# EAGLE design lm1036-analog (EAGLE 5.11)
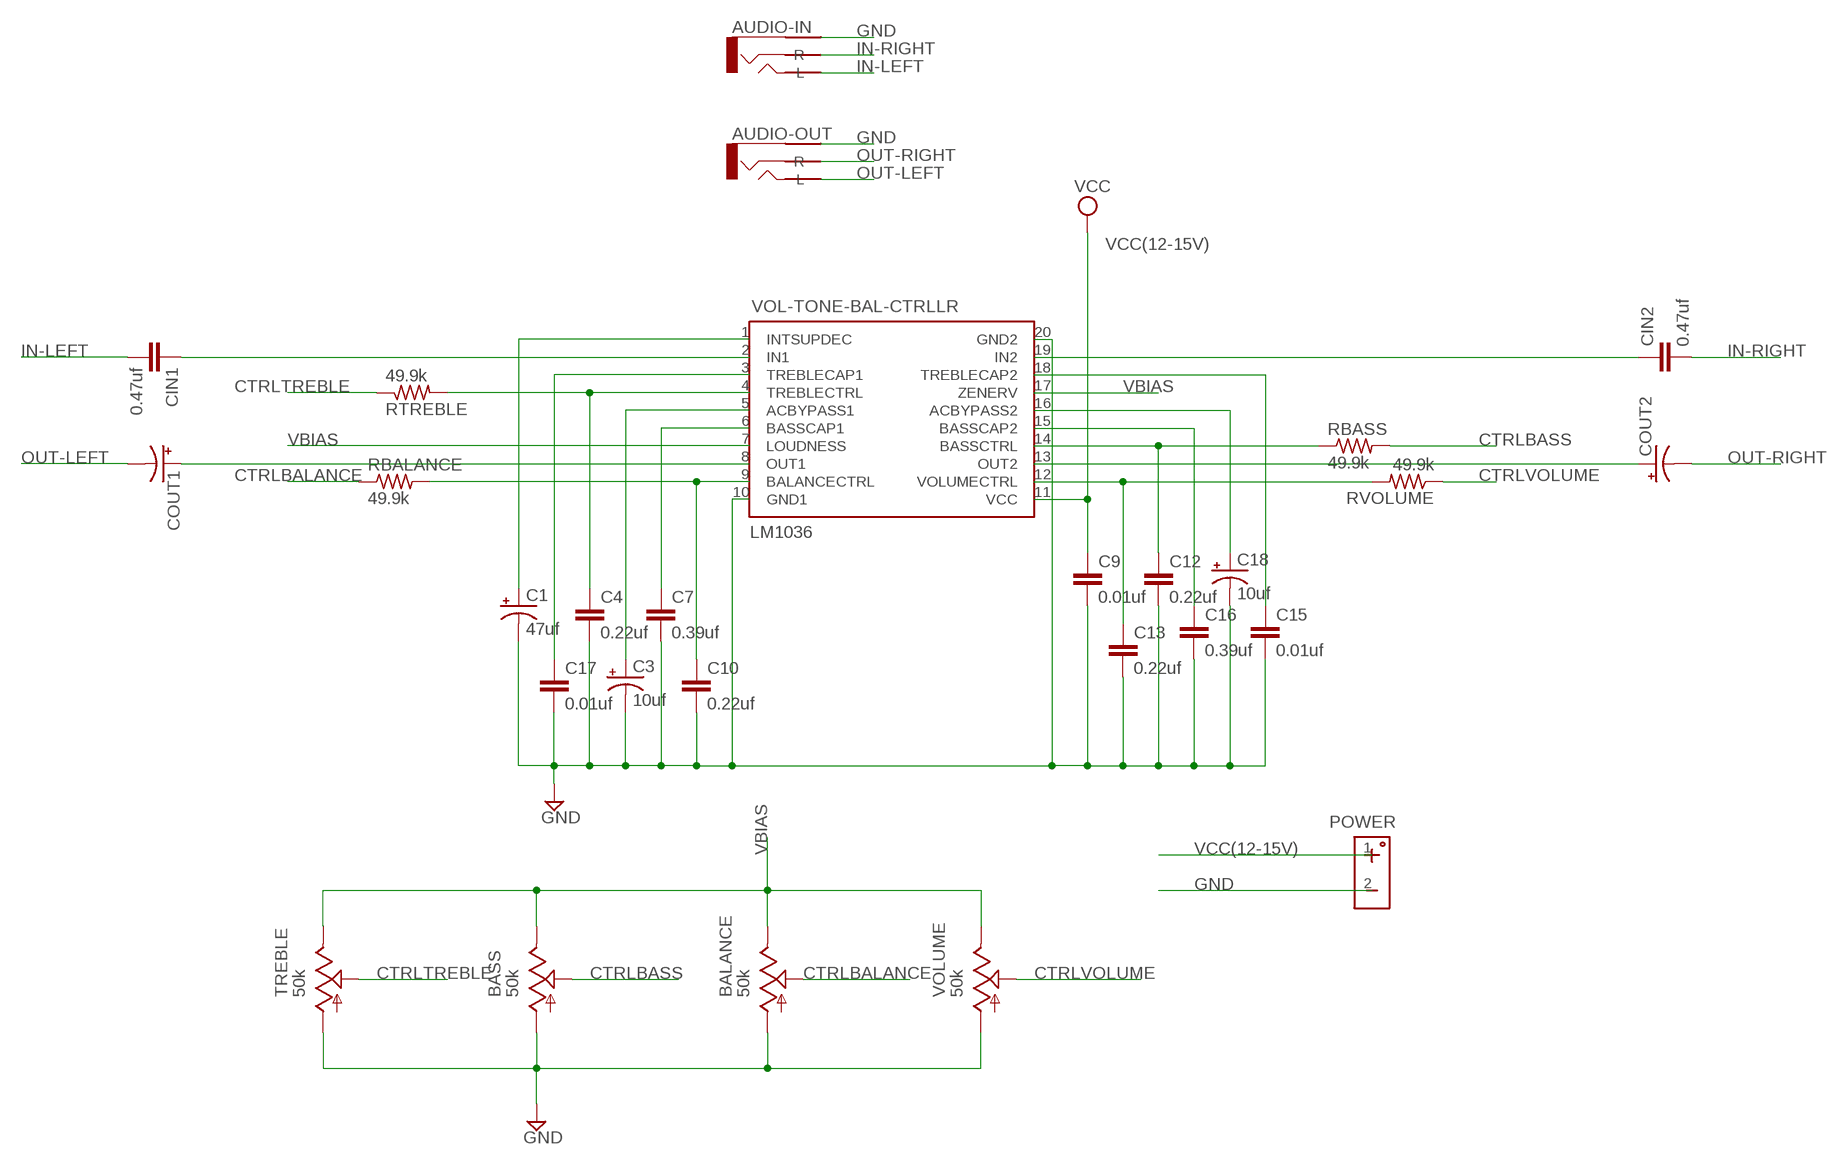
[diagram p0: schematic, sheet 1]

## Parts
AUDIO-IN  AUDIO-JACK-STEREO-3PIN948  [AUDIO-JACK-STEREO-3PIN-948]
AUDIO-OUT  AUDIO-JACK-STEREO-3PIN948  [AUDIO-JACK-STEREO-3PIN-948]
BALANCE  50k  POT-TRIM-0.35IN  [POT-TRIM-0.35IN]
BASS  50k  POT-TRIM-0.35IN  [POT-TRIM-0.35IN]
C1  47uf  CPOL-USE3.5-8  [E3,5-8]
C3  10uf  CPOL-USE3.5-8  [E3,5-8]
C4  0.22uf  C-EUC0805  [C0805]
C7  0.39uf  C-EUC1206  [C1206]
C9  0.01uf  C-EUC1206  [C1206]
C10  0.22uf  C-EUC0805  [C0805]
C12  0.22uf  C-EUC0805  [C0805]
C13  0.22uf  C-EUC0805  [C0805]
C15  0.01uf  C-EUC1206  [C1206]
C16  0.39uf  C-EUC1206  [C1206]
C17  0.01uf  C-EUC1206  [C1206]
C18  10uf  CPOL-USE3.5-8  [E3,5-8]
CIN1  0.47uf  C-EUC1206  [C1206]
CIN2  0.47uf  C-EUC1206  [C1206]
COUT1  CPOL-USE3.5-8  [E3,5-8]
COUT2  CPOL-USE3.5-8  [E3,5-8]
POWER  HEADER-POWER  [HEADER-POWER-PTH]
RBALANCE  49.9k  R-US_R0805  [R0805]
RBASS  49.9k  R-US_R0805  [R0805]
RTREBLE  49.9k  R-US_R0805  [R0805]
RVOLUME  49.9k  R-US_R0805  [R0805]
TREBLE  50k  POT-TRIM-0.35IN  [POT-TRIM-0.35IN]
VOL-TONE-BAL-CTRLLR  LM1036  [DIL20]
VOLUME  50k  POT-TRIM-0.35IN  [POT-TRIM-0.35IN]

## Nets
CTRLBALANCE: BALANCE.2(S) RBALANCE.1
CTRLBASS: BASS.2(S) RBASS.2
CTRLTREBLE: RTREBLE.1 TREBLE.2(S)
CTRLVOLUME: RVOLUME.1 VOLUME.2(S)
GND: AUDIO-IN.1(COM) AUDIO-OUT.1(COM) BALANCE.1(A) BASS.1(A) C1.- C3.- C4.2 C7.2 C9.2 C10.2 C12.2 C13.2 C15.2 C16.2 C17.2 C18.- POWER.2 TREBLE.1(A) VOL-TONE-BAL-CTRLLR.10(GND1) VOL-TONE-BAL-CTRLLR.20(GND2) VOLUME.1(A)
IN-LEFT: AUDIO-IN.2(L) CIN1.2
IN-RIGHT: AUDIO-IN.3(R) CIN2.2
N$1: C1.+ VOL-TONE-BAL-CTRLLR.1(INTSUPDEC)
N$2: CIN1.1 VOL-TONE-BAL-CTRLLR.2(IN1)
N$3: C17.1 VOL-TONE-BAL-CTRLLR.3(TREBLECAP1)
N$4: C7.1 VOL-TONE-BAL-CTRLLR.6(BASSCAP1)
N$5: COUT2.+ VOL-TONE-BAL-CTRLLR.13(OUT2)
N$6: C4.1 RTREBLE.2 VOL-TONE-BAL-CTRLLR.4(TREBLECTRL)
N$7: COUT1.+ VOL-TONE-BAL-CTRLLR.8(OUT1)
N$8: CIN2.1 VOL-TONE-BAL-CTRLLR.19(IN2)
N$9: C12.1 RBASS.1 VOL-TONE-BAL-CTRLLR.14(BASSCTRL)
N$10: C10.1 RBALANCE.2 VOL-TONE-BAL-CTRLLR.9(BALANCECTRL)
N$12: C3.+ VOL-TONE-BAL-CTRLLR.5(ACBYPASS1)
N$13: C16.1 VOL-TONE-BAL-CTRLLR.15(BASSCAP2)
N$14: C18.+ VOL-TONE-BAL-CTRLLR.16(ACBYPASS2)
N$16: C15.1 VOL-TONE-BAL-CTRLLR.18(TREBLECAP2)
N$18: C13.1 RVOLUME.2 VOL-TONE-BAL-CTRLLR.12(VOLUMECTRL)
OUT-LEFT: AUDIO-OUT.2(L) COUT1.-
OUT-RIGHT: AUDIO-OUT.3(R) COUT2.-
VBIAS: BALANCE.3(E) BASS.3(E) TREBLE.3(E) VOL-TONE-BAL-CTRLLR.7(LOUDNESS) VOL-TONE-BAL-CTRLLR.17(ZENERV) VOLUME.3(E)
VCC(12-15V): C9.1 POWER.1 VOL-TONE-BAL-CTRLLR.11(VCC) ; supply symbol labelled VCC

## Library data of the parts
AUDIO-IN AUDIO-OUT = trl:AUDIO-JACK-STEREO-3PIN
BALANCE BASS TREBLE VOLUME = trl:POT-TRIM-0.35IN
C1 C3 C18 COUT1 COUT2 = rcl:CPOL-US: POLARIZED CAPACITOR, American symbol
C4 C7 C9 C10 C12 C13 C15-C17 CIN1 CIN2 = rcl:C-EU: CAPACITOR, European symbol
POWER = trl:HEADER-POWER
RBALANCE RBASS RTREBLE RVOLUME = rcl:R-US_: RESISTOR, American symbol
VOL-TONE-BAL-CTRLLR = trl:LM1036

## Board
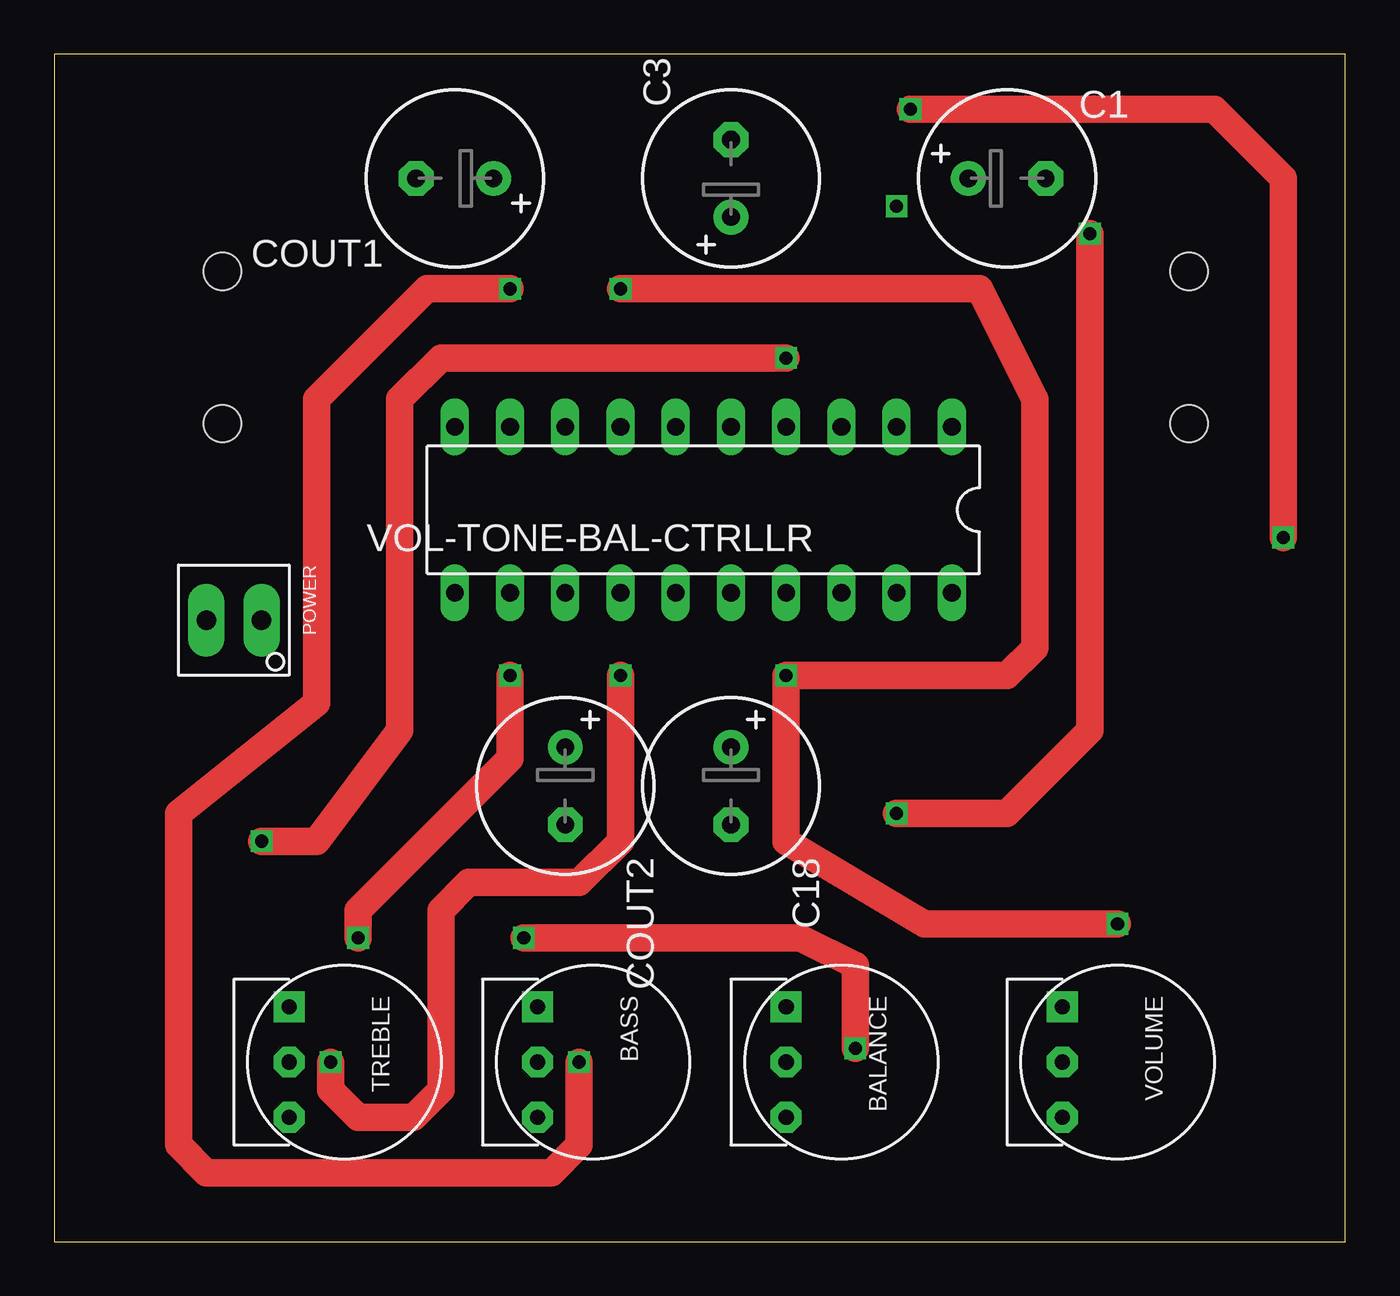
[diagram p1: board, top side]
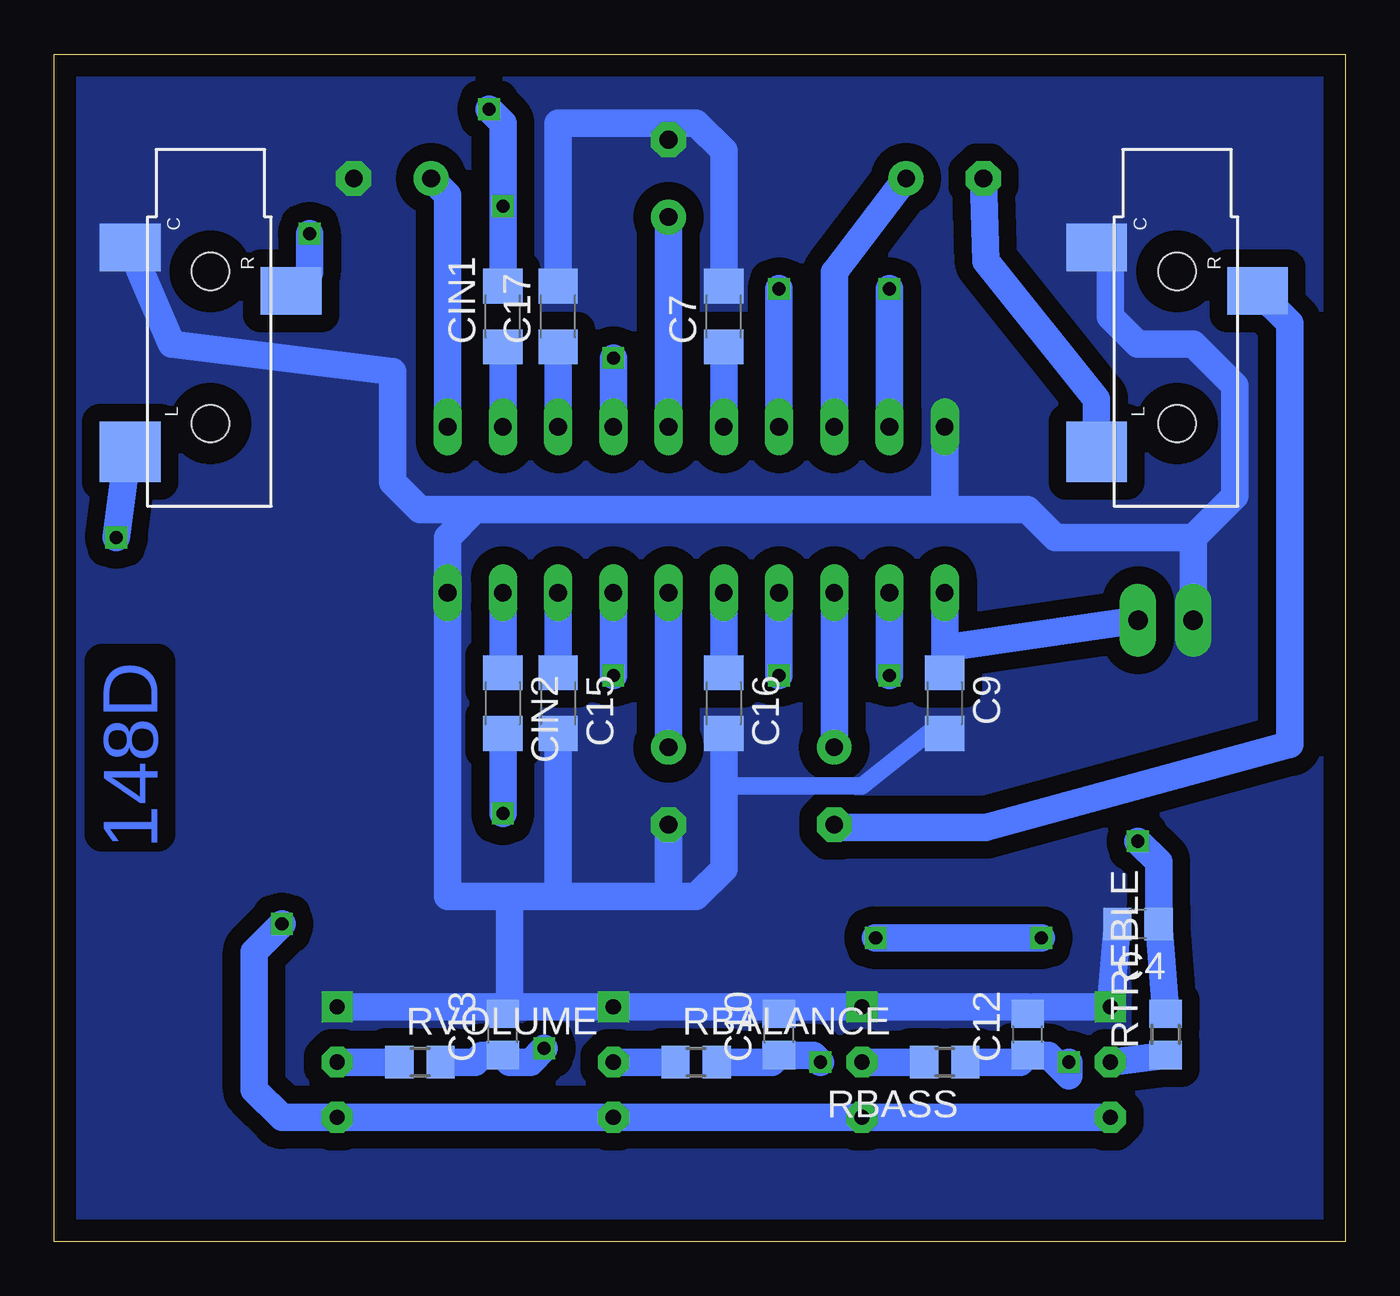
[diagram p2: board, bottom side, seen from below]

Size 59.36 x 54.6 mm. Coordinates in mm from the lower left corner, seen from the top.
Outline: 0,0 59.36,0 59.36,54.6 0,54.6 0,0
Copper layers (1*16): Top 0.035mm / dielectric 1.5mm / Bottom 0.035mm
Design rules "default": minimum track width 10mil, minimum drill 0.6mm, track to track 8mil, track to pad 8mil, pad to pad 8mil, via to via 8mil, smd to smd 8mil, copper to edge 40mil, drill to drill 8mil, minimum pad ring 10mil, minimum via ring 8mil, stop-mask expansion 4mil, vias tented up to drill 0mil, thermal gap 10mil

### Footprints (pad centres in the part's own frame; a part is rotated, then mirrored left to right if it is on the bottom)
AUDIO-JACK-STEREO-3PIN-948 = smd 2.2 x 2.8: 1 -3.81,-3.81; 3 -1.81,3.59 | smd 2.8 x 2.8: 2 5.59,-3.81 | hole 1.7: -2.71,-0.11; 4.29,-0.11
POT-TRIM-0.35IN = drill 0.7 pad 1.422 square: 1 -2.54,-3.81 | drill 0.7 pad 1.422 octagon: 2 0,-3.81; 3 2.54,-3.81
E3,5-8 = drill 0.813 pad 1.6 round: + -1.778,0 | drill 0.813 pad 1.6 octagon: - 1.778,0
C0805 = smd 1.3 x 1.5: 1 -0.95,0; 2 0.95,0
C1206 = smd 1.6 x 1.8: 1 -1.4,0; 2 1.4,0
HEADER-POWER-PTH = drill 0.9 pad 1.676 long: 1 0,1.27; 2 0,-1.27
R0805 = smd 1.3 x 1.5: 1 -0.95,0; 2 0.95,0
DIL20 = drill 0.813 long: 1 -11.43,-3.81; 2 -8.89,-3.81; 3 -6.35,-3.81; 4 -3.81,-3.81; 5 -1.27,-3.81; 6 1.27,-3.81; 7 3.81,-3.81; 8 6.35,-3.81; 9 8.89,-3.81; 10 11.43,-3.81; 11 11.43,3.81; 12 8.89,3.81; 13 6.35,3.81; 14 3.81,3.81; 15 1.27,3.81; 16 -1.27,3.81; 17 -3.81,3.81; 18 -6.35,3.81; 19 -8.89,3.81; 20 -11.43,3.81

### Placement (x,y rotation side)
AUDIO-IN  52.07,41.91 270 bottom
AUDIO-OUT  7.62,41.91 270 bottom
BALANCE  37.47,8.26 270 top
BASS  26.04,8.26 270 top
C1  43.81,48.9 0 top
C3  31.11,48.9 90 top
C4  9.53,14.61 180 bottom
C7  28.57,42.55 90 bottom
C9  18.41,24.77 270 bottom
C10  26.04,9.53 90 bottom
C12  14.61,9.53 90 bottom
C13  38.73,9.53 90 bottom
C15  36.2,24.77 270 bottom
C16  28.57,24.77 270 bottom
C17  36.2,42.55 90 bottom
C18  31.11,20.95 270 top
CIN1  38.73,42.55 90 bottom
CIN2  38.73,24.77 270 bottom
COUT1  18.41,48.9 180 top
COUT2  23.5,20.95 270 top
POWER  8.26,28.57 270 top
RBALANCE  29.84,8.26 0 bottom
RBASS  18.41,8.26 180 bottom
RTREBLE  8.26,9.53 90 bottom
RVOLUME  42.55,8.26 0 bottom
TREBLE  14.61,8.26 270 top
VOL-TONE-BAL-CTRLLR  29.84,33.66 180 top
VOLUME  50.16,8.26 270 top

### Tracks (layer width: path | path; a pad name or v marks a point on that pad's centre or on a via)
CTRLBALANCE
  Bottom 1.27: RBALANCE.1 BALANCE.2
CTRLBASS
  Bottom 1.27: RBASS.2 BASS.2
CTRLTREBLE
  Bottom 1.27: RTREBLE.1 TREBLE.2
CTRLVOLUME
  Bottom 1.27: RVOLUME.1 VOLUME.2
GND
  Bottom 0.813: AUDIO-OUT.1 12.06,46.35 | C9.2 19.18,23.36 22.23,20.95 28.57,20.95
  Bottom 1.27: 26.04,10.79 BASS.1 14.61,10.79 C12.2 14.29,10.79 TREBLE.1 C4.2 | 26.04,10.79 C10.2 | 26.04,10.79 BALANCE.1 38.41,10.79 | 38.41,10.79 C13.2 38.73,10.79 VOLUME.1 | 40.01,33.66 41.27,32.38 VOL-TONE-BAL-CTRLLR.20 41.27,15.88 38.73,15.88 | 40.01,33.66 42.55,33.66 43.81,34.92 43.81,40.01 53.98,41.27 AUDIO-IN.1 | C16.2 28.57,20.95 28.57,17.14 29.84,15.88 31.11,15.88 | 36.2,15.88 31.11,15.88 | 38.73,15.88 36.2,15.88 | 36.2,15.88 C15.2 | 31.11,15.88 C18.- | 31.11,51.44 36.2,51.44 C17.2 | 31.11,51.44 29.84,51.44 28.57,50.16 C7.2 | 31.11,51.44 C3.- | 38.41,10.79 38.41,15.55 38.73,15.88 | AUDIO-OUT.1 10.79,45.09 10.79,42.55 9.53,41.27 6.99,41.27 5.08,39.37 5.08,34.29 6.99,32.38 | 40.01,33.66 18.41,33.66 | 18.41,33.66 14.61,33.66 13.34,32.38 6.99,32.38 | 6.99,32.38 POWER.2 | 18.41,33.66 VOL-TONE-BAL-CTRLLR.10
  pour Bottom (isolate 0.813, no thermals): 0,54.61 59.05,54.61 59.05,0 0,0
IN-LEFT  (via drill 0.6)
  Top 1.27: v56.52,32.38 56.52,48.9 53.34,52.07 v39.37,52.07
  Bottom 1.27: CIN1.2 v38.73,47.62 38.73,51.44 v39.37,52.07 | v56.52,32.38 56.01,36.2 AUDIO-IN.2
IN-RIGHT  (via drill 0.6)
  Top 1.27: v38.73,19.68 43.81,19.68 47.62,23.5 v47.62,46.35
  Bottom 1.27: v38.73,19.68 CIN2.2 | v47.62,46.35 47.62,44.58 AUDIO-IN.3
N$1
  Bottom 1.27: VOL-TONE-BAL-CTRLLR.1 41.27,48.13 C1.+
N$2
  Bottom 1.27: VOL-TONE-BAL-CTRLLR.2 CIN1.1
N$3
  Bottom 1.27: VOL-TONE-BAL-CTRLLR.3 C17.1
N$4
  Bottom 1.27: VOL-TONE-BAL-CTRLLR.6 C7.1
N$5
  Bottom 1.27: COUT2.+ VOL-TONE-BAL-CTRLLR.13
N$6  (via drill 0.6)
  Top 1.27: v9.53,18.41 12.06,18.41 15.88,23.5 15.88,38.73 17.78,40.64 v33.66,40.64
  Bottom 1.27: RTREBLE.2 C4.1 8.57,17.46 v9.53,18.41 | v33.66,40.64 VOL-TONE-BAL-CTRLLR.4
N$7
  Bottom 1.27: VOL-TONE-BAL-CTRLLR.8 23.5,44.58 COUT1.+
N$8
  Bottom 1.27: CIN2.1 VOL-TONE-BAL-CTRLLR.19
N$9  (via drill 0.6)
  Top 1.27: v26.04,26.04 26.04,18.41 24.13,16.51 19.05,16.51 17.78,15.24 17.78,6.99 16.51,5.71 13.97,5.71 12.7,6.99 v12.7,8.26
  Bottom 1.27: v26.04,26.04 VOL-TONE-BAL-CTRLLR.14 | v12.7,8.26 12.7,7.62 13.65,8.57 C12.1 14.93,8.26 RBASS.1
N$10  (via drill 0.6)
  Top 1.27: v24.13,8.26 24.13,4.45 22.86,3.17 6.99,3.17 5.71,4.45 5.71,19.68 12.06,24.77 12.06,38.73 17.14,43.81 v20.95,43.81
  Bottom 1.27: v20.95,43.81 VOL-TONE-BAL-CTRLLR.9 | RBALANCE.2 26.36,8.26 C10.1 24.45,8.57 v24.13,8.26
N$12
  Bottom 1.27: VOL-TONE-BAL-CTRLLR.5 C3.+
N$13
  Bottom 1.27: C16.1 VOL-TONE-BAL-CTRLLR.15
N$14
  Bottom 1.27: C18.+ VOL-TONE-BAL-CTRLLR.16
N$16
  Bottom 1.27: C15.1 VOL-TONE-BAL-CTRLLR.18
N$18  (via drill 0.6)
  Top 1.27: v20.95,26.04 20.95,22.23 13.97,15.24 v13.97,13.97 | v36.83,8.89 36.83,12.7 34.29,13.97 v21.59,13.97
  Bottom 1.27: RVOLUME.2 40.01,8.26 39.69,8.57 C13.1 38.41,8.26 37.47,8.26 v36.83,8.89 | v20.95,26.04 VOL-TONE-BAL-CTRLLR.12 | v13.97,13.97 v21.59,13.97
OUT-LEFT
  Bottom 1.27: COUT1.- 16.51,45.09 11.43,38.73 AUDIO-OUT.2
OUT-RIGHT
  Bottom 1.27: COUT2.- 23.37,19.05 16.51,19.05 2.54,22.86 2.54,42.23 AUDIO-OUT.3
VBIAS  (via drill 0.6)
  Top 1.27: v48.9,14.61 40.01,14.61 33.66,18.41 v33.66,26.04 43.81,26.04 45.09,27.3 45.09,38.73 42.55,43.81 v26.04,43.81
  Bottom 1.27: TREBLE.3 BASS.3 BALANCE.3 VOLUME.3 48.9,5.71 50.16,6.99 50.16,13.34 v48.9,14.61 | v33.66,26.04 VOL-TONE-BAL-CTRLLR.17 | v26.04,43.81 VOL-TONE-BAL-CTRLLR.7
VCC(12-15V)
  Bottom 1.27: 18.41,27.3 C9.1 | 18.41,27.3 VOL-TONE-BAL-CTRLLR.11 | POWER.1 18.41,27.3

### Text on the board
Bottom: 148D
